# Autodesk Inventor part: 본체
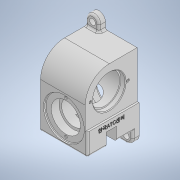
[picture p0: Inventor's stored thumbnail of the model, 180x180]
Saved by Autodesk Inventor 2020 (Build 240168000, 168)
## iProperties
Created: 2023-09
Part Number: 본체
Material: 일반
Document SubType Name: Modeling
Designer: oem
Density: 1 g/cm^3
Appearance: 기본값
Author: oem
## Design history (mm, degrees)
sketch "스케치1"
  geometry: L1 (-34.5, 40)-(34.5, 40); L2 (34.5, 40)-(34.5, -40); L3 (34.5, -40)-(-34.5, -40); L4 (-34.5, -40)-(-34.5, 40); L5 (-34.5, 40)-(34.5, -40); L6 (34.5, 40)-(-34.5, -40); 1 further point
  constraints: 12 end point, 2 midpoint, 2 parallel, 1 horizontal, 1 perpendicular
  dimensions: "d0" = 80 distance of L1.end L2.end; "d1" = 69 distance of L1.start L1.end
extrude "돌출1" new body sketch "스케치1" stored distance "d2" = 72; taper "d3" = 0 deg
sketch "스케치2"
  geometry: L1 (34.5, 40)-(34.5, -40) reference; L2 (34.5, 40)-(34.5, 40); L3 (71.5, 3)-(71.5, -40); L4 (71.5, -40)-(34.5, -40); L5 (34.5, -40)-(34.5, 40); A1 r 37 centre (34.5, 3) between (71.5, 3) and (34.5, 40); 4 further points
  constraints: 8 end point, 2 parallel, 2 point on circle, 2 point on line, 2 tangent, 1 centre point, 1 horizontal, 1 perpendicular
  dimensions: "d4" = 80 distance of point (71.5, 40) L3.end; "d5" = 37 distance of L1.start point (71.5, 40); "d6" = 37 radius of A1
extrude "돌출2" join sketch "스케치2" stored distance "d7" = 72; taper "d8" = 0 deg
sketch "스케치3"
  geometry: L1 (40, 71.5)-(-3, 71.5) reference; L2 (40, -34.5)-(-40, -34.5) reference; L3 (40, -34.5)-(-40, -34.5); L4 (-40, -34.5)-(-40, -0.5); L5 (-40, -0.5)-(40, -0.5); L6 (40, -0.5)-(40, -34.5); L7 (-40, -34.5)-(40, -34.5) reference; L8 (40, -34.5)-(40, 71.5) reference; L9 (40, 71.5)-(-3, 71.5) reference; L10 (-40, 34.5)-(-40, -34.5) reference; L11 (-40, -0.5)-(40, -0.5); L12 (40, -34.5)-(40, 71.5) reference; L13 (40, 71.5)-(-3, 71.5); L14 (-40, 34.5)-(-40, -4.319); L15 (-40, 34.5)-(-40, -34.5) reference; L16 (-3, 71.5)-(40, 71.5) reference; L17 (-3, 71.5)-(-3, 71.5); L18 (40, 71.5)-(40, -0.5); A1 r 37 centre (-3, 34.5) between (-3, 71.5) and (-40, 34.5) reference; A2 r 37 centre (-3, 34.5) between (-3, 71.5) and (-40, 34.5) reference; A3 r 37 centre (-3, 34.5) between (-3, 71.5) and (-40, 34.5); 5 further points
  constraints: 18 end point, 4 point on line, 3 collinear, 3 point on circle, 2 parallel, 2 perpendicular, 2 tangent, 1 centre point, 1 horizontal
  dimensions: "d10" = 72 distance between parallel lines of L1 L5; "d11" = 37 radius of A3 (derived)
extrude "돌출3" cut sketch "스케치3" distance "d12" = 3; taper "d13" = 0 deg
sketch "스케치5"
  geometry: L1 (-11, -14.5)-(5, -14.5); L2 (5, -14.5)-(5, -34.5); L3 (5, -34.5)-(-11, -34.5); L4 (-11, -34.5)-(-11, -14.5); L5 (-40, -34.5)-(40, -34.5) reference; A1 r 37 centre (-3, 34.5) between (-3, 71.5) and (-40, 34.5) reference; 1 further point
  constraints: 8 end point, 2 parallel, 1 collinear, 1 horizontal, 1 midpoint, 1 perpendicular, 1 vertical alignment
  dimensions: "d25" = 16 distance of L2.end L3.end; "d26" = 20 distance of L1.end L2.end
sketch "스케치6"
  geometry: L1 (72, 0)-(0, 0) reference; L2 (0, 0)-(72, 0); L3 (72, 0)-(72, -10); L4 (62, -20)-(10, -20); L5 (0, -10)-(0, 0); A1 r 10 centre (10, -10) between (0, -10) and (10, -20); A2 r 10 centre (62, -10) between (62, -20) and (72, -10); 4 further points
  constraints: 8 end point, 4 point on circle, 4 point on line, 4 tangent, 2 centre point, 2 parallel, 1 equal radius, 1 horizontal, 1 perpendicular
  dimensions: "d20" = 72 distance of point (72, -20) point (0, -20); "d21" = 20 distance of point (0, -20) L1.end; "d22" = 10 radius of A1
extrude "돌출5" join sketch "스케치6" distance "d23" = 10; taper "d24" = 0 deg
extrude "돌출6" cut sketch "스케치5" stored distance "d27" = 10; taper "d28" = 0 deg
sketch "스케치9"
  geometry: L1 (0, 43)-(69, 43) reference; L2 (0, 0)-(0, 43) reference; L3 (10, 43)-(0, 43) reference; L4 (0, 43)-(20, 43); L5 (20, 43)-(20, 33); L6 (20, 33)-(0, 33); L7 (0, 33)-(0, 43); 3 further points
  constraints: 8 end point, 2 parallel, 1 horizontal, 1 perpendicular
  dimensions: "d29" = 10 distance of L4.end L5.end; "d30" = 20 distance of L5.end L6.end
extrude "돌출7" join sketch "스케치9" distance "d31" = 20; taper "d32" = 0 deg
fillet "모깎기1" dims "d33" = 10
sketch "스케치12"
  geometry: C1 r 4.5 at (10, 10); A1 r 10 centre (10, 10) between (20, 10) and (0, 10) reference; 1 further point
  constraints: 1 centre point, 1 coincident
  dimensions: "d35" = 9 diameter of C1
extrude "돌출8" cut sketch "스케치12" distance "d36" = 20; taper "d37" = 0 deg
sketch "스케치13"
  geometry: C1 r 4.5 at (-62, -10); C2 r 4.5 at (-10, -10); A1 r 10 centre (-10, -10) between (-10, -20) and (0, -10) reference; A2 r 10 centre (-62, -10) between (-72, -10) and (-62, -20) reference; 1 further point
  constraints: 2 centre point, 2 coincident
  dimensions: "d38" = 9 diameter of C1; "d39" = 9 diameter of C2
extrude "돌출9" cut sketch "스케치13" distance "d40" = 20; taper "d41" = 0 deg
sketch "스케치14"
  geometry: L1 (-34.5, 40)-(34.5, 40) reference; L2 (-44.5, -40)-(81.5, -40) reference; L3 (0.5, 40)-(0.5, -40); L4 (-34.5, 11)-(-34.5, 40) reference; L5 (0.5, 40)-(32, 40); L6 (32, 37)-(23, 37); L7 (32, 37)-(32, 40); L8 (23, 37)-(23, 25); L9 (23, 25)-(0.5, 25); L10 (23, -32)-(23, -20); L11 (23, -20)-(0.5, -20); L12 (19, -20)-(19, 25); L13 (32, -32)-(32, -40); L14 (32, -40)-(0.5, -40); L15 (32, -32)-(23, -32); 3 further points
  constraints: 24 end point, 10 point on line, 6 perpendicular, 4 vertical, 1 collinear
  dimensions: "d49" = 35 distance between parallel lines of L3 L4; "d52" = 12 distance of L6.end L8.end; "d55" = 45 diameter of L8 L3; "d60" = 45 diameter of L10 L3; "d61" = 37 diameter of L12 L3; "d62" = 63 diameter of L7 L3; "d63" = 3 distance of L6.start L5.end; "d64" = 63 diameter of L13 L3; "d65" = 8 distance between parallel lines of L2 L15; "d66" = 12 distance between parallel lines of L15 L11
revolve "회전1" sketch "스케치14" stored, may be unused: angle "d67" = 90 deg
chamfer "모따기2" distance "d84" = 1; stored, may be unused: second distance "d85" = 2, angle "d86" = 45 deg
sketch "스케치17"
  geometry: C1 r 22.5 at (0, 0) reference; C2 r 30.5 at (0, 0) reference; A1 r 26 centre (0, 0) between (0, 26) and (0, -26)
  constraints: 2 point on circle, 2 vertical alignment, 1 centre point, 1 coincident
  dimensions: "d90" = 52 diameter of A1
hole "구멍1" sketch "스케치17" at (0, 26), (0, -26) diameter "d91" = 3.242; stored, may be unused: countersink angle "d95" = 60 deg, drill point angle "d97" = 118 deg; dims "d92" = 8, "d93" = 4.25, "d94" = 2, "d96" = 10
sketch "스케치18" dims "d99" = 52
  geometry: C1 r 22.5 at (0, 0) reference; C2 r 30.5 at (0, 0) reference; C3 r 22.5 at (0, 0) reference; C4 r 1.621 at (0, -26) reference; 3 further points
  constraints: 3 vertical alignment, 2 coincident, 2 other
hole "구멍2" sketch "스케치18" at (0, -26), (0, 26) diameter "d100" = 3.242; stored, may be unused: countersink angle "d104" = 60 deg, drill point angle "d106" = 118 deg; dims "d101" = 8, "d102" = 4.25, "d103" = 2, "d105" = 10
node "작업 평면2"
sketch "스케치19"
  geometry: L1 (69, 69)-(0, 69); L2 (72, 0)-(0, 0) reference; L3 (69, 106)-(69, 34) reference; L4 (62, 94)-(62, 92); L5 (62, 92)-(22, 92); L6 (22, 92)-(22, 87.5); L7 (21, 86.5)-(7.3, 86.5); L8 (7, 86.2)-(7, 84.5); L9 (7, 84.5)-(3, 84.5); L10 (3, 84.5)-(3, 69); L11 (62, 94)-(69, 94); L12 (69, 94)-(69, 69); L13 (21, 86.5)-(22, 87.5); A1 r 0.3 centre (7.3, 86.2) between (7.3, 86.5) and (7, 86.2); 3 further points
  constraints: 22 end point, 7 perpendicular, 7 point on line, 2 point on circle, 2 tangent, 1 centre point, 1 collinear, 1 horizontal, 1 vertical
  dimensions: "d124" = 69 distance between parallel lines of L2 L1; "d137" = 31 diameter of L9 L1; "d138" = 35 diameter of L7 L1; "d139" = 46 diameter of L5 L1; "d140" = 50 diameter of L11 L1; "d141" = 7 distance of L4.start L11.end; "d142" = 40 distance of L4.end L5.end; "d143" = 4 distance of L8.end L9.end; "d144" = 15 distance of point (22, 86.5) point (7, 86.5); "d145" = 0.3 radius of A1 (derived); "d146" = 1 distance of L7.start point (22, 86.5); "d147" = 1 distance of L6.end point (22, 86.5) (= d146)
revolve "회전3" sketch "스케치19" stored, may be unused: angle "d136" = 90 deg
chamfer "모따기3" distance "d148" = 1; stored, may be unused: second distance "d149" = 2, angle "d150" = 45 deg
sketch "스케치20"
  geometry: C1 r 26 at (-3, 34.5) reference; A1 r 37 centre (-3, 34.5) between (-3, 71.5) and (-40, 34.5) reference; A2 r 29 centre (-3, 34.5) between (26, 34.5) and (-32, 34.5); 1 further point
  constraints: 2 horizontal alignment, 2 point on circle, 1 centre point, 1 coincident
  dimensions: "d151" = 58 diameter of A2
hole "구멍3" sketch "스케치20" at (26, 34.5), (-32, 34.5) diameter "d152" = 3.242; stored, may be unused: countersink angle "d156" = 60 deg, drill point angle "d158" = 118 deg; dims "d153" = 8, "d154" = 4.25, "d155" = 2, "d157" = 10
node "작업 평면3"
sketch "스케치21"
  geometry: L1 (-40, -34.5)-(-11, -34.5) reference; C1 r 26 at (-3, 34.5) reference; 2 further points
  constraints: 1 vertical alignment, 1 other
  dimensions: "d160" = 27 distance from line of L1 point (-3, -7.5)
feature "엠보싱1" sketch "스케치21" dims "d0" = 80, "d1" = 69, "d161" = 0.5, "d162" = 0
fillet "모깎기2" dims "d172" = 3
fillet "모깎기3" dims "d173" = 3
fillet "모깎기4" dims "d174" = 3
fillet "모깎기5" dims "d175" = 3
sketch "스케치23"
  geometry: L1 (-3, 8)-(-72, 8) reference; L2 (-72, 0)-(-72, 16) reference; L3 (-10, -17)-(-10, 33) reference; L4 (-10, -15)-(-10, 31) reference; L5 (-50, 0.993)-(-50, 15.007) reference; 4 further points
  constraints: 2 point on line, 1 midpoint, 1 vertical alignment
  dimensions: "d179" = 50 distance of point (-61, 8) point (-11, 8); "d180" = 25 horizontal distance of point (-36, 5) point (-11, 8)
hole "구멍5" sketch "스케치23" at (-11, 8), (-61, 8) diameter "d181" = 3.242; stored, may be unused: countersink angle "d185" = 60 deg, drill point angle "d187" = 118 deg; dims "d182" = 8, "d183" = 4.25, "d184" = 2, "d186" = 10
node "솔리드1"
node "투영된 루프1"
node "투영된 루프2"
feature "A9D066F2-1C7D-4E18-AEED-F7BC21143FA4" dims "d91" = 3.242, "d92" = 8, "d93" = 4.25, "d94" = 2, "d95" = 60 deg, "d96" = 10, "d97" = 118 deg
other parameters: "d109" = -37, "d159" = 5
